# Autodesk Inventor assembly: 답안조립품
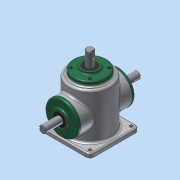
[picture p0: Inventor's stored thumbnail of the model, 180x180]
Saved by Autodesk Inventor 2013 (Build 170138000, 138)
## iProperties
Created: 2015-10
Part Number: 답안조립품
Document SubType Name: Assembly
Designer: Administrator
Author: Administrator
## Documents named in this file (14)
- C:\Users\Administrator\Desktop\451008V1019\답안조립품.iam
- C:\Users\Administrator\Desktop\451008V1019\1-본체.ipt
- C:\Users\Administrator\Desktop\451008V1019\서브 축.ipt
- 서브 축.ipt
- C:\Users\Administrator\Desktop\451008V1019\베어링 6203.ipt
- C:\Users\Administrator\Desktop\451008V1019\키 4x4.ipt
- C:\Users\Administrator\Desktop\451008V1019\서브 베벨기어.ipt
- C:\Users\Administrator\Desktop\451008V1019\커버.ipt
- C:\Users\Administrator\Desktop\451008V1019\오일실.ipt
- C:\Users\Administrator\Desktop\451008V1019\메인 축.ipt
- 메인 축.ipt
- C:\Users\Administrator\Desktop\451008V1019\키 5x5.ipt
- C:\Users\Administrator\Desktop\451008V1019\메인 베벨기어.ipt
- C:\Users\Administrator\Desktop\451008V1019\M4.ipt
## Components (13 placed, 2 different names)
1. 1-본체:1 — 각도:7, 각도:9
2. M4:1
3. M4:4
4. M4:5
5. M4:6
6. M4:2
7. M4:7
8. M4:8
9. M4:9
10. M4:3
11. M4:10
12. M4:11
13. M4:12
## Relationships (2: Angle 2)
- 각도:7 [Angle]: 1-본체:1
- 각도:9 [Angle]: 1-본체:1
